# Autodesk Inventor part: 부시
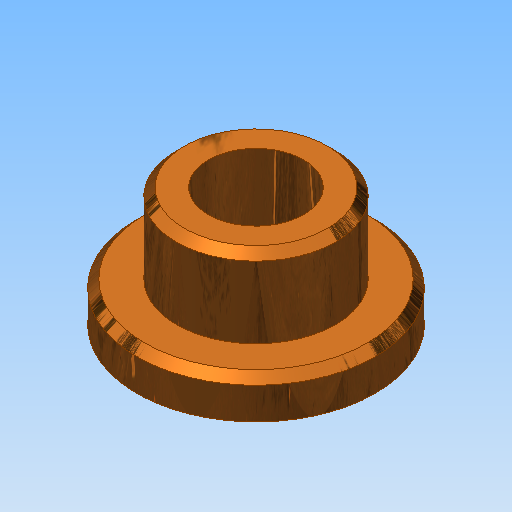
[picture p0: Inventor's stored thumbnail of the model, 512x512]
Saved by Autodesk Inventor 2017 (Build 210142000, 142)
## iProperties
Created: 2016-02
Part Number: 부시
Material: 스테인리스강
Document SubType Name: Modeling
Designer: mduedu
Density: 8.08 g/cm^3
Appearance: 금속 1600F 열
Author: mduedu
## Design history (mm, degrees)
sketch "스케치1"
  geometry: C1 r 15 at (0, 0); 1 further point
  constraints: 1 centre point, 1 coincident
  dimensions: "d0" = 30 diameter of C1
extrude "돌출1" new body sketch "스케치1" distance "d1" = 5; taper "d2" = 0 deg
sketch "스케치2"
  geometry: C1 r 10 at (0, 0); 1 further point
  constraints: 1 centre point, 1 coincident
  dimensions: "d3" = 20 diameter of C1
extrude "돌출2" join sketch "스케치2" distance "d4" = 10; taper "d5" = 0 deg
hole "구멍1" diameter "d8" = 12; stored, may be unused: countersink angle "d12" = 90 deg, drill point angle "d14" = 118 deg; dims "d9" = 6, "d10" = 4, "d11" = 2, "d13" = 8, "d15" = 10, "d16" = 10
chamfer "모따기1" distance "d17" = 1; stored, may be unused: second distance "d18" = 2, angle "d19" = 45 deg
chamfer "모따기2" distance "d20" = 1; stored, may be unused: second distance "d21" = 2, angle "d22" = 45 deg
chamfer "모따기3" distance "d23" = 1; stored, may be unused: second distance "d24" = 2, angle "d25" = 45 deg
node "솔리드1"
